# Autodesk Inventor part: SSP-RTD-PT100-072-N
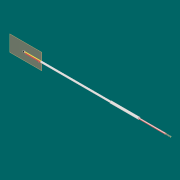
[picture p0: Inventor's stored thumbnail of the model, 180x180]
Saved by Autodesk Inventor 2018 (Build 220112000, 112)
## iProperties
Created: 2017-06
Part Number: SSP-RTD-PT100-072-N
Material: Generic
Document SubType Name: Modeling
Designer: JN
Density: 1 g/cm^3
Appearance: Smooth - Black
Author: JN
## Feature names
1. Extrusion1
2. Extrusion2
3. Extrusion3
4. Extrusion7
5. Extrusion8
6. Sweep1
7. Extrusion10
8. Loft8
9. Loft9
10. Loft10
11. Extrusion11
12. Extrusion12
13. Sweep5
14. Extrusion15
## Parameters: d0 = 50.8 mm, d1 = 25.4 mm, d2 = 0.0889 mm, d3 = 0, d4 = 2.54 mm, d5 = 2.286 mm, d6 = 2.032 mm, d7 = 1.016 mm, d8 = 0, d9 = 0.508 mm, d12 = 0.635 mm, d13 = 0, d14 = 0.9525 mm, d79 = 1.016 mm, d80 = 26.162 mm, d81 = 0, d82 = 1.016 mm, d84 = 26.162 mm, d85 = 0, d86 = -0.508 mm, d92 = 0, d93 = 0, d96 = 1.016 mm, d99 = 60 deg, d100 = 60 deg, d101 = 2.54 mm, d102 = 152.4 mm, d103 = 0, d104 = 1.016 mm, d105 = 0.508 mm, d108 = 1.016 mm, d109 = 1.016 mm, d110 = 44.45 mm, d111 = 1.016 mm, d112 = 1.016 mm, d113 = 1.016 mm, d114 = 0, d115 = 90 deg, d116 = 0, d117 = 90 deg, d118 = 0, d119 = 90 deg, d120 = 0, d121 = 90 deg, d122 = 0, d123 = 90 deg, d124 = 0, d125 = 90 deg, d126 = 0, d127 = 90 deg, d128 = 0, d129 = 90 deg, d130 = 0, d131 = 90 deg, d132 = 0.508 mm, d133 = 0.508 mm, d134 = 0.508 mm, d135 = 8.46667 mm, d136 = 0, d137 = 30 deg, d138 = 2.032 mm, d140 = 20.32 mm, d141 = 0, d142 = 1.016 mm, d148 = 0, d149 = 0, d155 = 0.9525 mm, d159 = 0.127 mm, d163 = 0.127 mm, d164 = 0.635 mm, d167 = 0.635 mm, d168 = -41.91 mm, d169 = 3.4798 mm, d170 = 44.45 mm, d171 = 0
